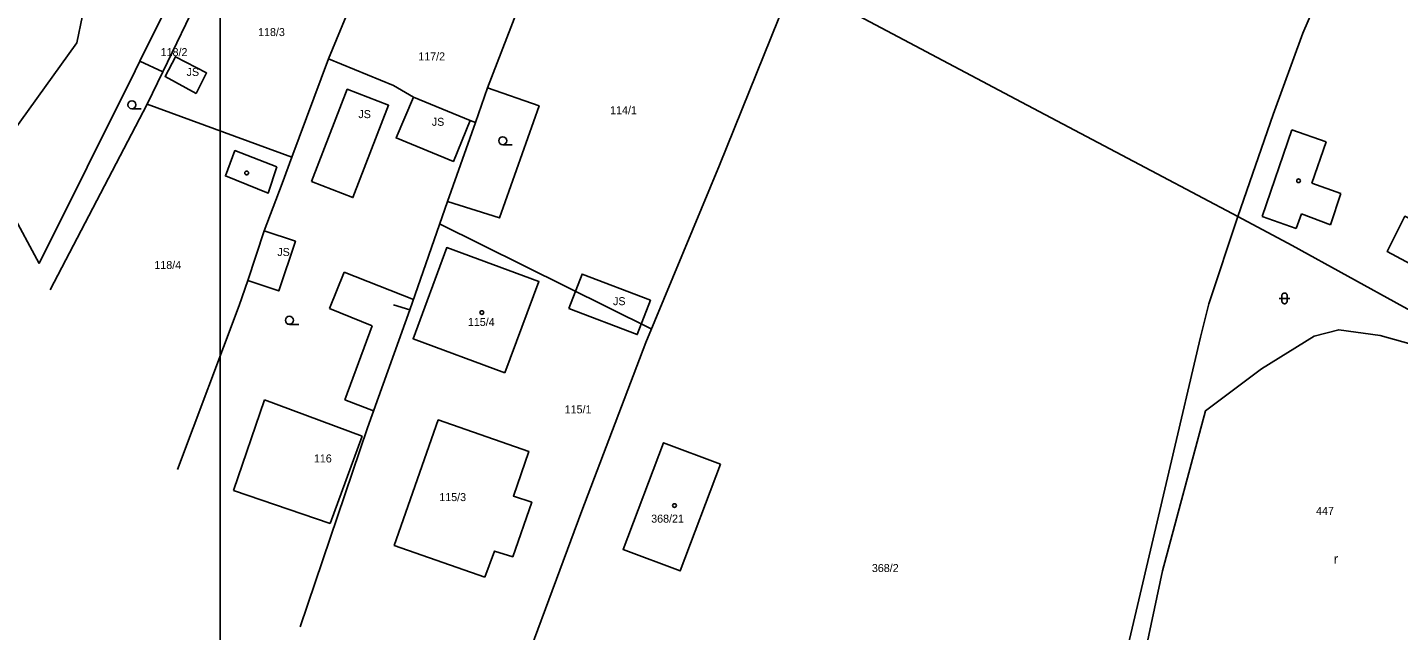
# Model space of a CAD drawing. Extents: x -836615 to -835459, y -1070675 to -1070205.
# Drawn here: x -836521.2 to -836392.7, y -1070473.1 to -1070416.5 of the extents above; entities that cross this region are included whole.
import ezdxf

# ---------------------------------------------------------------- set-up
doc = ezdxf.new("R2010")
doc.units = 0
for name, color, linetype in [('BodPole_body', 7, 'Continuous'), ('Budovy_hranice', 7, 'Continuous'), ('Budovy_kody', 7, 'Continuous'), ('OstPloch_hranice', 7, 'Continuous'), ('OstPloch_kody', 7, 'Continuous'), ('RuianPar_popis', 7, 'Continuous'), ('Stavby_hr_stav', 7, 'Continuous'), ('Stavby_kody', 7, 'Continuous'), ('Stavby_linie', 7, 'Continuous')]:
    doc.layers.add(name, color=color, linetype=linetype)

msp = doc.modelspace()

# ---------------------------------------------------------------- linework, layer by layer
at = {"layer": 'BodPole_body'}
msp.add_lwpolyline([(-836503.12, -1070278.67), (-836206.12, -1070278.67), (-836206.12, -1070488.67), (-836503.12, -1070488.67)], close=True, dxfattribs=at)
at = {"layer": 'Budovy_hranice'}
for p, q in [((-836405.46, -1070434.26), (-836402.66, -1070426.14)), ((-836402.66, -1070426.14), (-836399.46, -1070427.25)), ((-836399.46, -1070427.25), (-836400.8, -1070431.15)), ((-836400.8, -1070431.15), (-836398.08, -1070432.09)), ((-836398.08, -1070432.09), (-836399.05, -1070435.03)), ((-836401.78, -1070434.02), (-836402.26, -1070435.37)), ((-836399.05, -1070435.03), (-836401.78, -1070434.02)), ((-836402.26, -1070435.37), (-836405.46, -1070434.26))]:
    msp.add_line(p, q, dxfattribs=at)
for points in [[(-836497.79, -1070429.61), (-836498.6, -1070432.07), (-836502.61, -1070430.46), (-836501.73, -1070428.08), (-836497.79, -1070429.61)], [(-836476.42, -1070448.9), (-836473.24, -1070440.36), (-836481.87, -1070437.18), (-836485.02, -1070445.71), (-836476.42, -1070448.9)], [(-836478.29, -1070468.05), (-836486.79, -1070465.09), (-836482.66, -1070453.32), (-836474.18, -1070456.28), (-836475.62, -1070460.46), (-836473.91, -1070461.04), (-836475.68, -1070466.15), (-836477.41, -1070465.61), (-836478.29, -1070468.05)], [(-836456.23, -1070457.47), (-836461.55, -1070455.46), (-836465.35, -1070465.47), (-836460, -1070467.47), (-836456.23, -1070457.47)]]:
    msp.add_lwpolyline(points, dxfattribs=at)
at = {"layer": 'Budovy_kody'}
for p, q in [((-836462.71, -1070444.79), (-836482.54, -1070434.95)), ((-836491.48, -1070439.48), (-836492.86, -1070442.88)), ((-836484.99, -1070442.05), (-836491.48, -1070439.48)), ((-836492.86, -1070442.88), (-836488.87, -1070444.52)), ((-836488.87, -1070444.52), (-836491.42, -1070451.45)), ((-836498.96, -1070451.44), (-836501.86, -1070459.93)), ((-836489.8, -1070454.85), (-836498.96, -1070451.44)), ((-836491.42, -1070451.45), (-836488.74, -1070452.46)), ((-836492.8, -1070463.03), (-836489.8, -1070454.85)), ((-836501.86, -1070459.93), (-836492.8, -1070463.03))]:
    msp.add_line(p, q, dxfattribs=at)
for centre in [(-836500.62, -1070430.18), (-836402.04, -1070430.91), (-836478.58, -1070443.26), (-836460.53, -1070461.35)]:
    msp.add_circle(centre, 0.175, dxfattribs=at)
at = {"layer": 'OstPloch_hranice'}
msp.add_line((-836479.68, -1070425.25), (-836479.19, -1070425.44), dxfattribs=at)
msp.add_lwpolyline([(-836382.62, -1070447.97), (-836384.12, -1070448.01), (-836386.69, -1070447.56), (-836394.4, -1070445.42), (-836398.28, -1070444.88), (-836400.59, -1070445.48), (-836405.51, -1070448.52), (-836410.77, -1070452.46), (-836414.78, -1070467.48), (-836419.92, -1070491.57), (-836422.14, -1070507.07), (-836424.43, -1070527.13), (-836426.86, -1070555.21), (-836427.73, -1070571.17), (-836426.62, -1070578.67)], dxfattribs=at)
at = {"layer": 'OstPloch_kody'}
for p, q in [((-836510.51, -1070424.17), (-836511.38, -1070424.17)), ((-836475.74, -1070427.54), (-836476.62, -1070427.54)), ((-836403.86, -1070441.93), (-836402.86, -1070441.93)), ((-836403.61, -1070442.18), (-836403.61, -1070441.68)), ((-836403.11, -1070441.68), (-836403.11, -1070442.18)), ((-836495.74, -1070444.37), (-836496.62, -1070444.37))]:
    msp.add_line(p, q, dxfattribs=at)
for points in [[(-836403.36, -1070441.43), (-836403.41, -1070441.43), (-836403.45, -1070441.45), (-836403.5, -1070441.47), (-836403.54, -1070441.5), (-836403.57, -1070441.54), (-836403.59, -1070441.59), (-836403.61, -1070441.63), (-836403.61, -1070441.68)], [(-836403.36, -1070441.43), (-836403.31, -1070441.43), (-836403.27, -1070441.45), (-836403.22, -1070441.47), (-836403.18, -1070441.5), (-836403.15, -1070441.54), (-836403.13, -1070441.59), (-836403.11, -1070441.63), (-836403.11, -1070441.68)], [(-836403.36, -1070442.43), (-836403.41, -1070442.43), (-836403.45, -1070442.41), (-836403.5, -1070442.39), (-836403.54, -1070442.36), (-836403.57, -1070442.32), (-836403.59, -1070442.27), (-836403.61, -1070442.23), (-836403.61, -1070442.18)], [(-836403.11, -1070442.18), (-836403.11, -1070442.23), (-836403.13, -1070442.27), (-836403.15, -1070442.32), (-836403.18, -1070442.36), (-836403.22, -1070442.39), (-836403.27, -1070442.41), (-836403.31, -1070442.43), (-836403.36, -1070442.43)]]:
    msp.add_lwpolyline(points, dxfattribs=at)
for centre in [(-836511.38, -1070423.79), (-836476.62, -1070427.16), (-836496.62, -1070443.99)]:
    msp.add_ellipse(centre, major_axis=(0.375, 0), ratio=0.999999, dxfattribs=at)
at = {"layer": 'Stavby_hr_stav'}
for points in [[(-836505.36, -1070422.73), (-836504.37, -1070420.8), (-836507.3, -1070419.3), (-836508.26, -1070421.15), (-836505.36, -1070422.73)], [(-836494.55, -1070430.98), (-836491.2, -1070422.33), (-836487.32, -1070423.83), (-836490.67, -1070432.48), (-836494.55, -1070430.98)], [(-836479.68, -1070425.25), (-836484.98, -1070423.09), (-836486.62, -1070426.9), (-836481.24, -1070429.09), (-836479.68, -1070425.25)], [(-836387.27, -1070436.75), (-836392.07, -1070434.23), (-836393.73, -1070437.54), (-836388.97, -1070440.09), (-836387.27, -1070436.75)], [(-836498.99, -1070435.6), (-836496.06, -1070436.58), (-836497.61, -1070441.23), (-836500.5, -1070440.27), (-836498.99, -1070435.6)], [(-836470.42, -1070442.88), (-836469.19, -1070439.66), (-836462.79, -1070442.11), (-836464.02, -1070445.33), (-836470.42, -1070442.88)]]:
    msp.add_lwpolyline(points, dxfattribs=at)
at = {"layer": 'Stavby_linie'}
for p, q in [((-836492.95, -1070419.48), (-836487.03, -1070405.19)), ((-836516.53, -1070417.97), (-836516.02, -1070415.43)), ((-836524.99, -1070429.71), (-836516.53, -1070417.97)), ((-836510.63, -1070419.69), (-836508.49, -1070420.71)), ((-836492.95, -1070419.48), (-836496.39, -1070428.69)), ((-836492.95, -1070419.48), (-836486.87, -1070421.98)), ((-836511.08, -1070420.6), (-836520.08, -1070438.65)), ((-836486.87, -1070421.98), (-836484.98, -1070423.09)), ((-836522.71, -1070433.72), (-836520.08, -1070438.65))]:
    msp.add_line(p, q, dxfattribs=at)
for points in [[(-836407.72, -1070434.26), (-836404.42, -1070424.71), (-836401.63, -1070417.07), (-836396.94, -1070406.16), (-836393.4, -1070397.9)], [(-836511.08, -1070420.6), (-836510.63, -1070419.69), (-836500.91, -1070400.2)], [(-836498.55, -1070400.92), (-836505, -1070413.5), (-836508.49, -1070420.71), (-836509.95, -1070423.73)], [(-836470.4, -1070403.24), (-836475.34, -1070415.17), (-836478.04, -1070422.2), (-836479.19, -1070425.44), (-836481.8, -1070432.85), (-836476.93, -1070434.4), (-836473.21, -1070423.9), (-836478.04, -1070422.2)], [(-836407.72, -1070434.26), (-836402.65, -1070436.98), (-836392.21, -1070442.72), (-836384.11, -1070447.06), (-836383.25, -1070443.91), (-836379.69, -1070432.5), (-836376.35, -1070424), (-836370.7, -1070410.27), (-836369.71, -1070407.51)], [(-836449.39, -1070412.25), (-836456.32, -1070429.46), (-836463.2, -1070446.07), (-836469.22, -1070461.85), (-836476.75, -1070482.14), (-836479.99, -1070490.54)], [(-836407.72, -1070434.26), (-836415.3, -1070430.25), (-836428, -1070423.55), (-836445.87, -1070414.08), (-836449.39, -1070412.25)], [(-836496.39, -1070428.69), (-836509.95, -1070423.73), (-836519.03, -1070441.12)], [(-836498.99, -1070435.6), (-836497.3, -1070431.18), (-836496.39, -1070428.69)], [(-836481.8, -1070432.85), (-836485.34, -1070443), (-836486.87, -1070442.53)], [(-836427.9, -1070546.1), (-836426.76, -1070535.49), (-836425.46, -1070522.59), (-836424.54, -1070513.97), (-836423.07, -1070499.04), (-836421.63, -1070492.15), (-836418.84, -1070478.02), (-836414.08, -1070457.69), (-836411.22, -1070445.56), (-836410.44, -1070442.44), (-836407.72, -1070434.26)], [(-836507.11, -1070457.97), (-836501.33, -1070442.61), (-836500.5, -1070440.27)], [(-836485.34, -1070443), (-836489.31, -1070454.06), (-836495.6, -1070472.71)]]:
    msp.add_lwpolyline(points, dxfattribs=at)

# ---------------------------------------------------------------- texts
at = {"layer": 'OstPloch_kody'}
msp.add_text('r', height=0.9, dxfattribs=at).set_placement((-836398.74, -1070466.79))
at = {"layer": 'RuianPar_popis'}
for s, p in [('118/3', (-836499.55, -1070417.35)), ('118/2', (-836508.68, -1070419.23)), ('117/2', (-836484.54, -1070419.63)), ('114/1', (-836466.56, -1070424.67)), ('118/4', (-836509.27, -1070439.18)), ('115/4', (-836479.89, -1070444.52)), ('115/1', (-836470.82, -1070452.71)), ('116', (-836494.32, -1070457.31)), ('115/3', (-836482.57, -1070460.93)), ('368/21', (-836462.71, -1070462.95)), ('447', (-836400.4, -1070462.22)), ('368/2', (-836442.03, -1070467.58))]:
    msp.add_text(s, height=0.75, dxfattribs=at).set_placement(p)
at = {"layer": 'Stavby_kody'}
for p in [(-836506.25, -1070421.09), (-836490.15, -1070425.04), (-836483.27, -1070425.76), (-836497.75, -1070437.96), (-836466.29, -1070442.57)]:
    msp.add_text('JS', height=0.75, dxfattribs=at).set_placement(p)

doc.saveas('drawing.dxf')
